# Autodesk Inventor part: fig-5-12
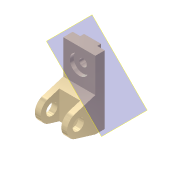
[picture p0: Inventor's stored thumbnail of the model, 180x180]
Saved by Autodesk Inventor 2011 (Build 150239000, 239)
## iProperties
Shininess: 65.0
Angle Display Precision: 2
Document Length Units: 11269
Document Angle Units: 11279
Document Time Units: 11290
Document Mass Units: 11283
Document Length Units Precision: 3
Document Angle Units Precision: 2
Compacted: False
Created: 2001-11
Part Number: fig-5-12
Document SubType Name: Modeling
Designer: Renu Muthoo
Density: 1 g/cm^3
Density: 0.0
Volumn: 0.0
Area: 0.0
PropertySet Name: Model Information
Control State: 0
Master: False
Checked Out: False
Author: Renu Muthoo
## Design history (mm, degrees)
node "Sketch1"
sketch "Sketch2"
  geometry: L1 (33.257, 104.664)-(33.257, -75.336); L2 (33.257, -75.336)-(8.257, -75.336); L3 (8.257, -75.336)-(-45.451, -59.045); L4 (-45.451, -1.628)-(8.257, 14.664); L5 (8.257, 14.664)-(8.257, 104.664); L6 (8.257, 104.664)-(33.257, 104.664); C1 r 15 at (-36.743, -30.336); A1 r 30 centre (-36.743, -30.336) between (-45.451, -1.628) and (-45.451, -59.045)
  constraints: 12 end point, 2 centre point, 2 equal length, 2 parallel, 2 point on circle, 2 tangent, 1 coincident, 1 perpendicular, 1 vertical
  dimensions: "d0" = 180 distance of L1.start L1.end; "d1" = 30 radius of A1; "d2" = 25 distance of L5.end L1.start; "d3" = 45 distance from line of L2 A1.centre; "d4" = 70 distance from line of L1 A1.centre; "d5" = 30 diameter of C1
extrude "Extrusion1" new body sketch "Sketch2" distance "d6" = 85; taper "d7" = 0 deg
workplane "Work Plane1"
sketch "Sketch3"
  geometry: L1 (15, 62.364)-(70, 62.364); L2 (70, 62.364)-(70, -52.386); L3 (70, -52.386)-(15, -52.386); L4 (15, -52.386)-(15, 62.364); L5 (0, -45)-(0, -28.708) reference
  constraints: 8 end point, 2 parallel, 1 horizontal, 1 perpendicular
  dimensions: "d8" = 55 distance of L1.start L1.end; "d9" = 15 distance between parallel lines of L5 L4
extrude "Extrusion2" cut sketch "Sketch3" distance "d10" = 50; taper "d11" = 0 deg
sketch "Sketch4"
  geometry: L1 (0, 25)-(85, 25) reference; L2 (0, 0)-(0, 25) reference; L3 (20, 25)-(65, 25); L4 (65, 25)-(65, 35); L5 (65, 35)-(20, 35); L6 (20, 35)-(20, 25)
  constraints: 8 end point, 2 parallel, 1 horizontal, 1 perpendicular, 1 point on line
  dimensions: "d12" = 45 distance of L4.end L5.end; "d13" = 10 distance of L3.end L4.end; "d14" = 20 distance between parallel lines of L2 L6
extrude "Extrusion3" join sketch "Sketch4" stored distance "d15" = 50; taper "d16" = 0 deg
sketch "Sketch5"
  geometry: L1 (85, 0)-(85, 90) reference; L2 (0, 90)-(85, 90) reference; 1 further point
  dimensions: "d17" = 42 distance from line of L2 point (42.5, 48); "d18" = 42.5 distance from line of L1 point (42.5, 48)
hole "Hole1" sketch "Sketch5" at (42.5, 48) diameter "d19" = 20; stored, may be unused: countersink angle "d23" = 82 deg, drill point angle "d25" = 118 deg; dims "d20" = 6, "d21" = 50, "d22" = 10, "d24" = 8
workplane "Work Plane8"
body "Solid1"
other parameters: "d28" = 135 deg
